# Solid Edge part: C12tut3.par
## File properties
Author: CADCIM
Template: ansi part.par
Last saved by: CADCIM
Revision: 8
Application: Solid Edge
Accuracy: 0.990
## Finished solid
Body 1: solid body, 13 faces, 19 edges, 8 vertices.
  Faces by surface: plane 9, cylinder 4
  Edges by curve: line 10, circle 8, ellipse 1
Bounding box of the edges (mm): 31.750 x 82.544 x 31.750, from (-15.875, -77.8163, -15.875) to (15.875, 4.7283, 15.875).
Cylindrical faces by radius (mm): R5.5944 x1, R6.35 x1, R7.9375 x1, R15.875 x1
Planar faces by outward normal: +x 1, +y 1, +z 1, -x 1, -y 4, oblique 1
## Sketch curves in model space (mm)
line (-22.2359, -0.0325, 12.7) -> (-22.2334, -4.7925, 7.935)
line (-22.2322, -77.8163, 5.5531) -> (-22.2323, -0.0289, 5.77)
line (-22.2262, -77.8103, -5.6356) -> (-22.2263, -0.0229, -5.5751)
line (-22.2326, -68.2917, 6.3138) -> (-22.2326, -77.8167, 6.3087)
line (-22.2326, -77.8167, 6.3087) -> (-22.2258, -77.8099, -6.3913)
line (-22.2258, -68.2849, -6.3862) -> (-22.2258, -77.8099, -6.3913)
line (-22.2376, -0.0342, 15.875) -> (-22.2208, -0.0174, -15.875)
line (-22.2376, 4.7283, 15.8775) -> (-22.2376, -0.0342, 15.875)
line (-22.2376, 4.7283, 15.8775) -> (-22.2208, 4.7451, -15.8725)
line (-22.2208, 4.7451, -15.8725) -> (-22.2208, -0.0174, -15.875)
line (-22.225, -0.0216, -7.9375) -> (-22.225, -68.2841, -7.9737)
line (-22.2334, -0.03, 7.9375) -> (-22.2334, -68.2925, 7.9013)
line (-22.2334, -68.2925, 7.9013) -> (-22.225, -68.2841, -7.9737)
line (0, 0, 22.225) -> (0, 0, -22.225)
line (22.225, 0, 0) -> (-22.225, 0, 0)
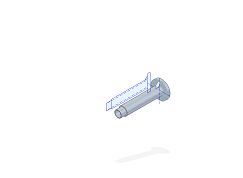
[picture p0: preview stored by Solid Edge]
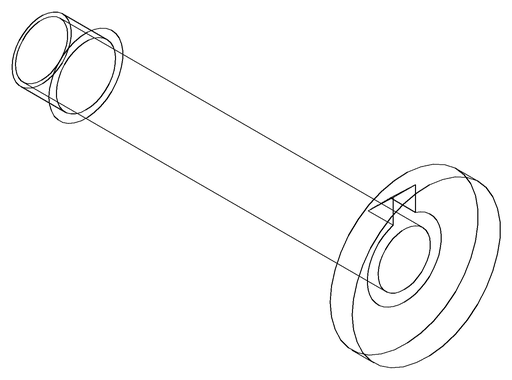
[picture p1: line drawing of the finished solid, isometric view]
